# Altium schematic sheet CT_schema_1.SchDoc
size 715 x 456 mm
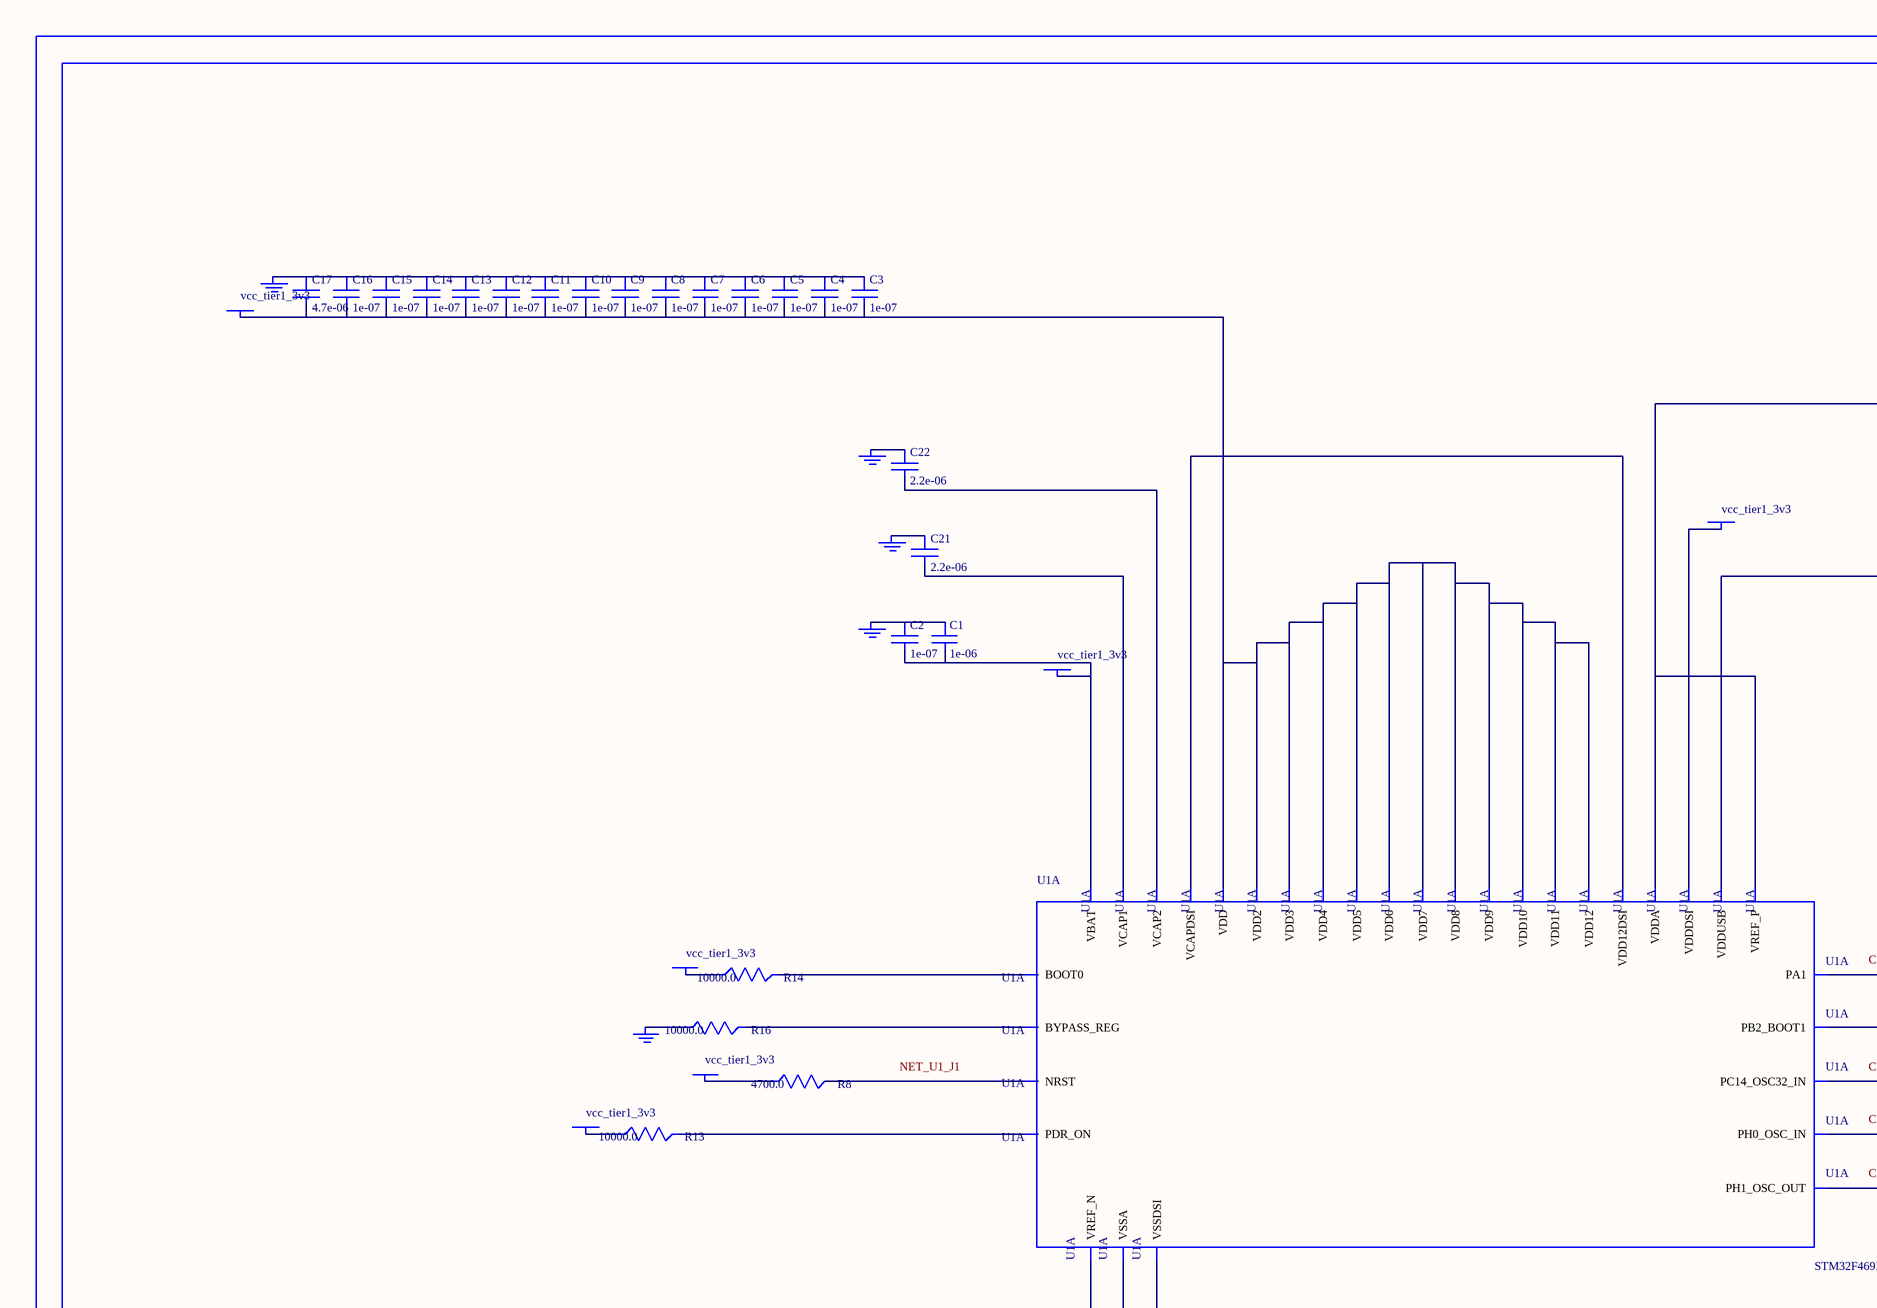
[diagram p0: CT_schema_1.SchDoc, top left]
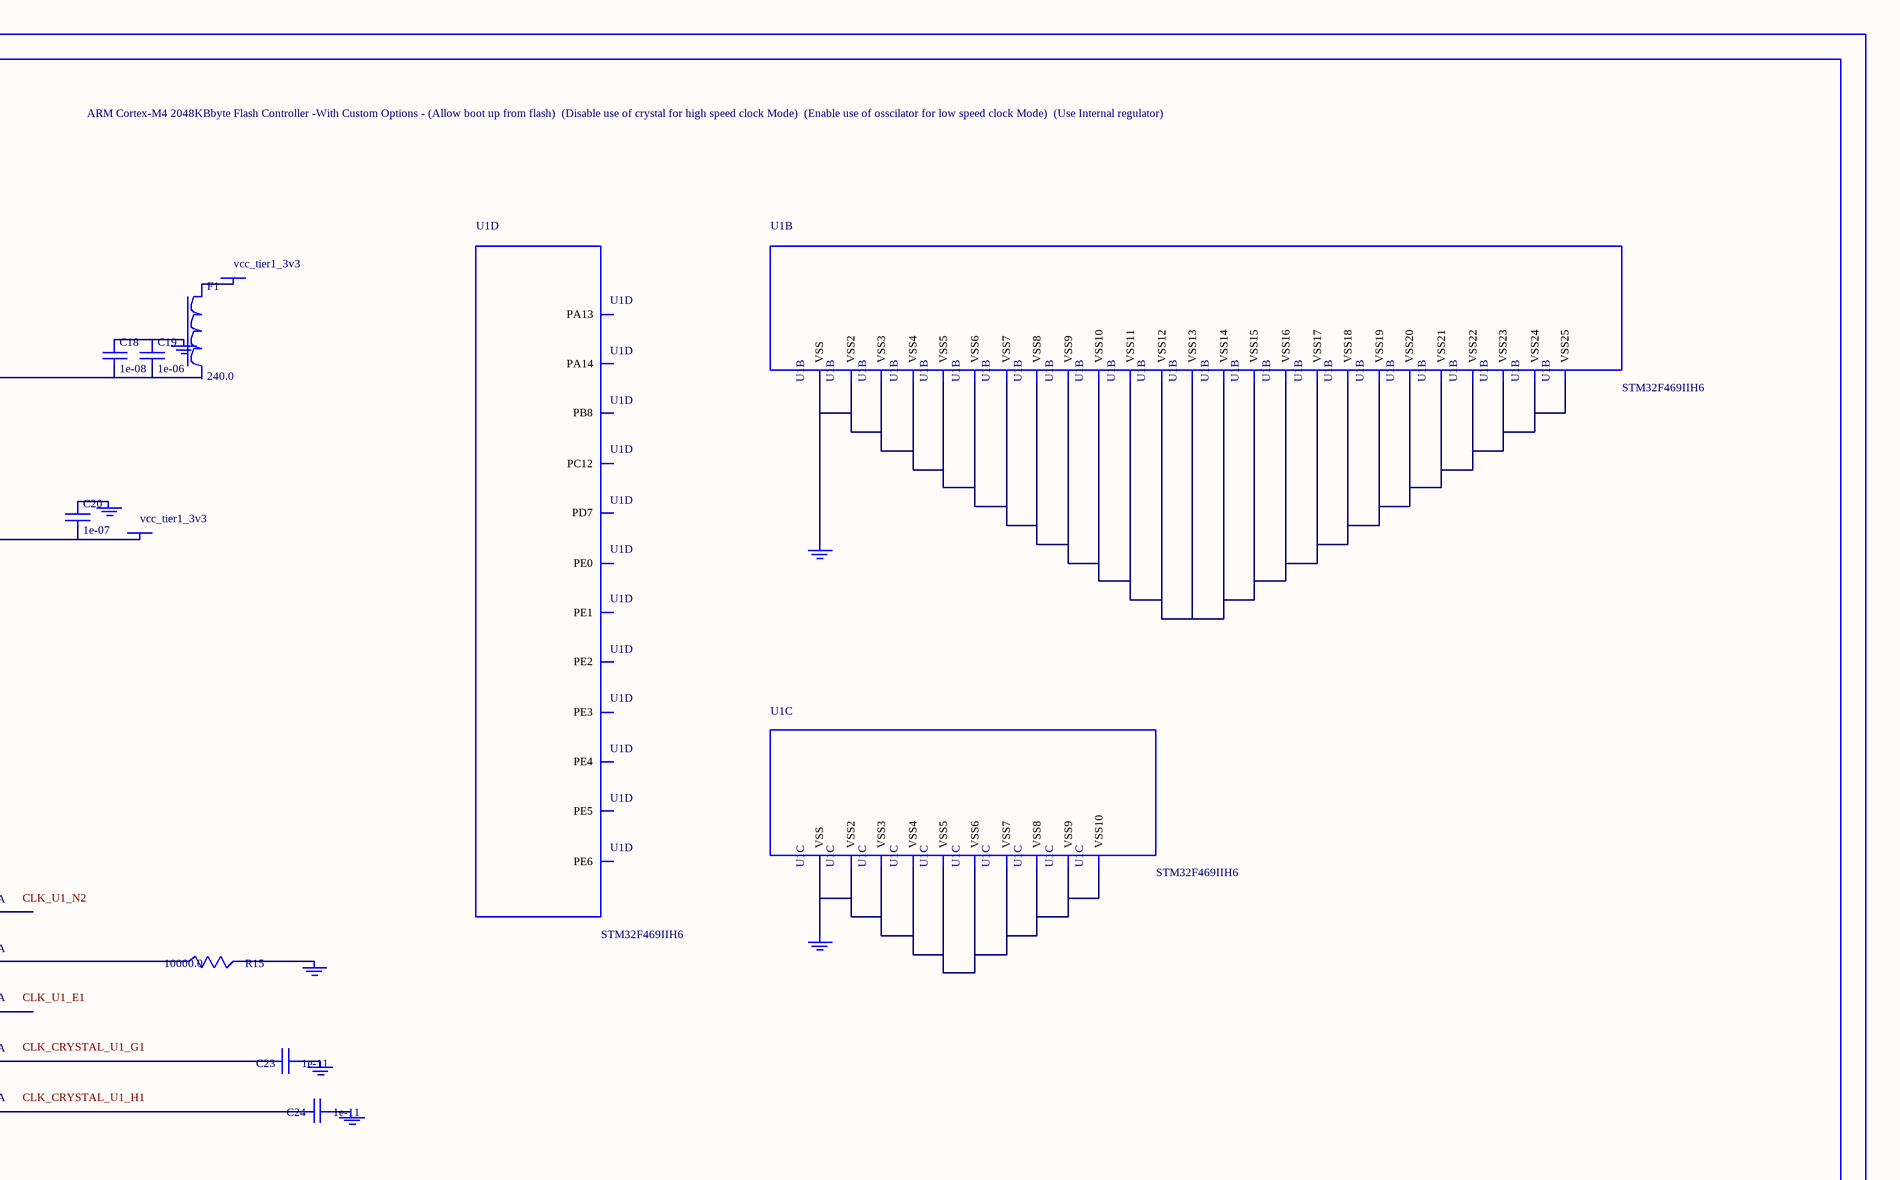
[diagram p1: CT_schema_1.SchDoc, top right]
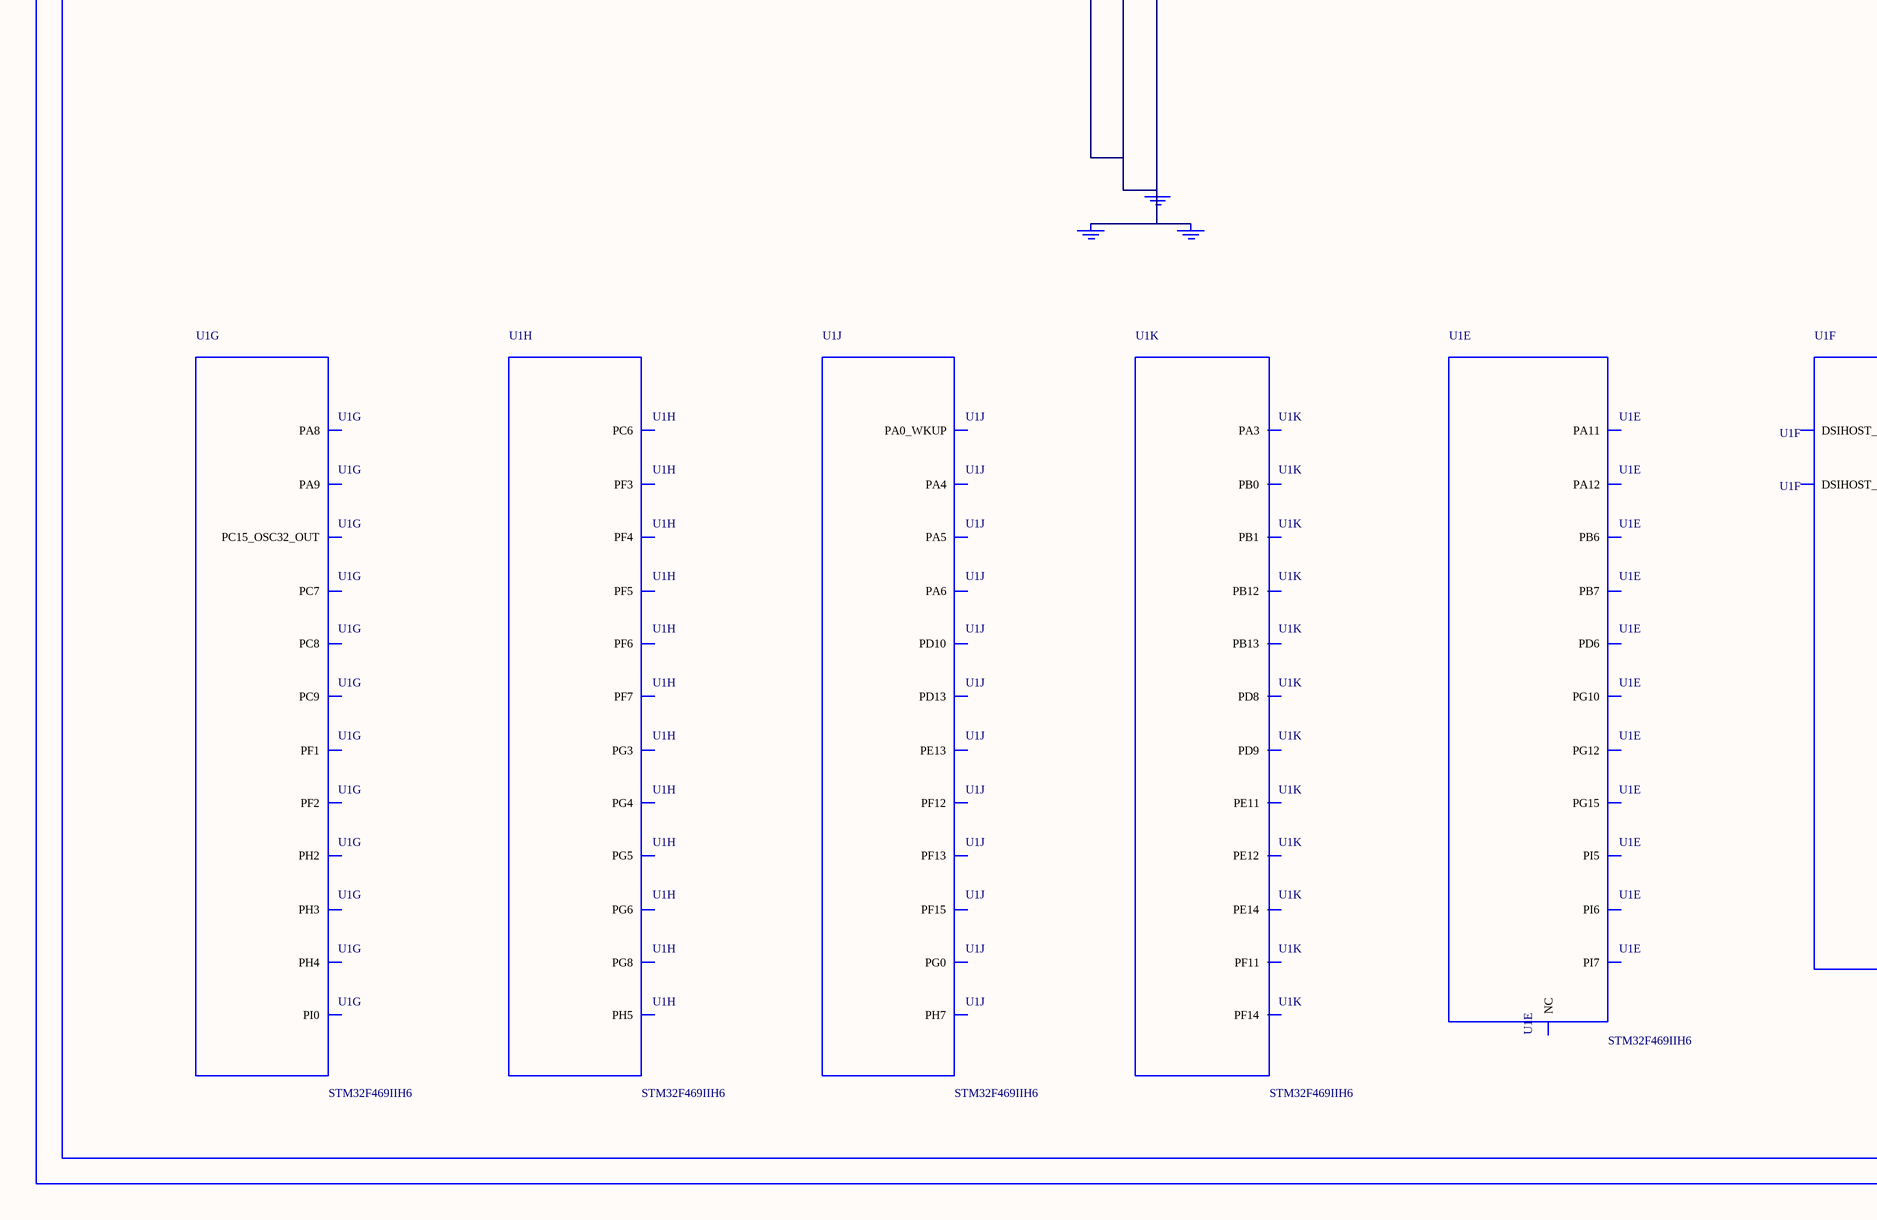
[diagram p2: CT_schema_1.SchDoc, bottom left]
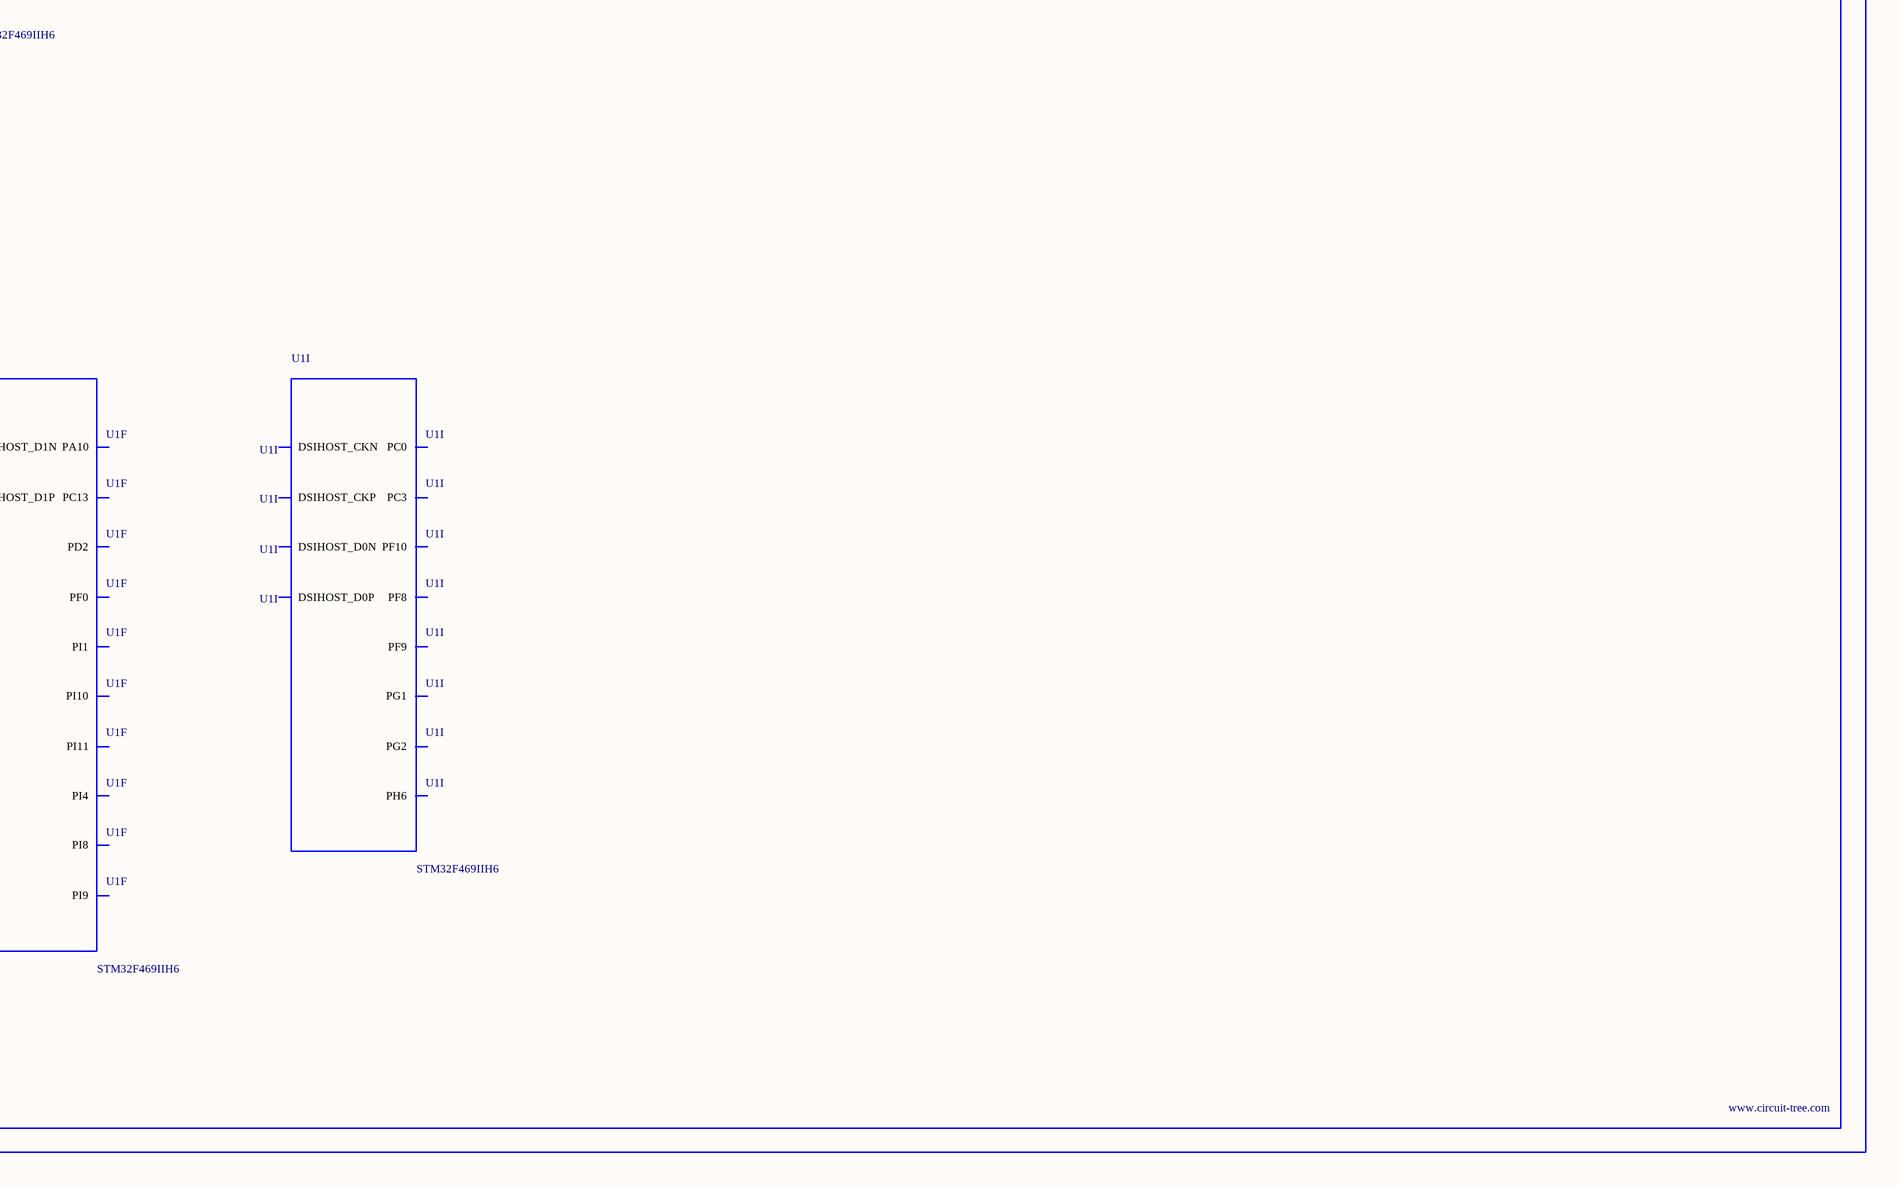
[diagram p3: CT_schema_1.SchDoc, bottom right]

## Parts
BORDER0  (no value)
C1  1e-06  [C0603]
C2  1e-07  [C0603]
C3  1e-07  [C0603]
C4  1e-07  [C0603]
C5  1e-07  [C0603]
C6  1e-07  [C0603]
C7  1e-07  [C0603]
C8  1e-07  [C0603]
C9  1e-07  [C0603]
C10  1e-07  [C0603]
C11  1e-07  [C0603]
C12  1e-07  [C0603]
C13  1e-07  [C0603]
C14  1e-07  [C0603]
C15  1e-07  [C0603]
C16  1e-07  [C0603]
C17  4.7e-06  [C0603]
C18  1e-08  [C0603]
C19  1e-06  [C0603]
C20  1e-07  [C0603]
C21  2.2e-06  [C0603]
C22  2.2e-06  [C0603]
C23  1e-11  [C0402]
C24  1e-11  [C0402]
F1  240.0  [L0603]
GND_INSTANCE_0_0  (no value)
GND_INSTANCE_0_1  (no value)
GND_INSTANCE_0_2  (no value)
GND_INSTANCE_0_3  (no value)
GND_INSTANCE_0_4  (no value)
GND_INSTANCE_0_5  (no value)
GND_INSTANCE_0_6  (no value)
GND_INSTANCE_0_7  (no value)
GND_INSTANCE_0_8  (no value)
GND_INSTANCE_0_9  (no value)
GND_INSTANCE_0_10  (no value)
GND_INSTANCE_0_11  (no value)
GND_INSTANCE_0_12  (no value)
GND_INSTANCE_0_13  (no value)
GND_INSTANCE_0_14  (no value)
POWER_INSTANCE_0_0  vcc_tier1_3v3
POWER_INSTANCE_0_1  vcc_tier1_3v3
POWER_INSTANCE_0_2  vcc_tier1_3v3
POWER_INSTANCE_0_3  vcc_tier1_3v3
POWER_INSTANCE_0_4  vcc_tier1_3v3
POWER_INSTANCE_0_5  vcc_tier1_3v3
POWER_INSTANCE_0_6  vcc_tier1_3v3
POWER_INSTANCE_0_7  vcc_tier1_3v3
R8  4700.0  [R0603]
R13  10000.0  [R0603]
R14  10000.0  [R0603]
R15  10000.0  [R0603]
R16  10000.0  [R0603]
U1  STM32F469IIH6  [UFBGA176]  (parts A,B,C,D,E,F,G,H,I,J,K of 17)

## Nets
NetC1_1: C1.1 C2.1 GND_INSTANCE_0_0.0(GND)
NetC1_2: C1.2 C2.2 POWER_INSTANCE_0_0.0(PWR) U1.C1(VBAT)
NetC3_1: C3.1 C4.1 C5.1 C6.1 C7.1 C8.1 C9.1 C10.1 C11.1 C12.1 C13.1 C14.1 C15.1 C16.1 C17.1 GND_INSTANCE_0_2.0(GND)
NetC3_2: C3.2 C4.2 C5.2 C6.2 C7.2 C8.2 C9.2 C10.2 C11.2 C12.2 C13.2 C14.2 C15.2 C16.2 C17.2 POWER_INSTANCE_0_2.0(PWR) U1.C5(VDD) U1.C7(VDD2) U1.C8(VDD3) U1.C9(VDD4) U1.F3(VDD5) U1.G3(VDD7) U1.G13(VDD6) U1.J13(VDD8) U1.K4(VDD9) U1.N8(VDD11) U1.N9(VDD12) U1.N10(VDD10)
NetC18_1: C18.1 C19.1 GND_INSTANCE_0_1.0(GND)
NetC18_2: C18.2 C19.2 U1.P1(VREF_P) U1.R1(VDDA)
NetC20_1: C20.1 GND_INSTANCE_0_3.0(GND)
NetC20_2: C20.2 POWER_INSTANCE_0_4.0(PWR) U1.H13(VDDUSB)
NetC21_1: C21.1 GND_INSTANCE_0_6.0(GND)
NetC21_2: C21.2 U1.M10(VCAP1)
NetC22_1: C22.1 GND_INSTANCE_0_7.0(GND)
NetC22_2: C22.2 U1.F13(VCAP2)
NetC23_1: C23.1 GND_INSTANCE_0_8.0(GND)
NetC23_2: C23.2 U1.G1(PH0_OSC_IN)
NetC24_1: C24.1 GND_INSTANCE_0_9.0(GND)
NetC24_2: C24.2 U1.H1(PH1_OSC_OUT)
NetF1_1: F1.1 POWER_INSTANCE_0_1.0(PWR)
NetGND_INSTANCE_0_4_0: GND_INSTANCE_0_4.0(GND) R15.2
NetGND_INSTANCE_0_5_0: GND_INSTANCE_0_5.0(GND) R16.1
NetGND_INSTANCE_0_10_0: GND_INSTANCE_0_10.0(GND) GND_INSTANCE_0_11.0(GND) GND_INSTANCE_0_12.0(GND) U1.H12(VSSDSI) U1.M1(VSSA) U1.N1(VREF_N)
NetGND_INSTANCE_0_13_0: GND_INSTANCE_0_13.0(GND) U1.D5(VSS) U1.D7(VSS2) U1.D8(VSS3) U1.D9(VSS4) U1.F2(VSS7) U1.F6(VSS8) U1.F7(VSS9) U1.F8(VSS10) U1.F9(VSS11) U1.F10(VSS5) U1.F12(VSS6) U1.G2(VSS14) U1.G6(VSS15) U1.G7(VSS16) U1.G8(VSS17) U1.G9(VSS18) U1.G10(VSS12) U1.G12(VSS13) U1.H6(VSS20) U1.H7(VSS21) U1.H8(VSS22) U1.H9(VSS23) U1.H10(VSS19) U1.J6(VSS25) U1.J10(VSS24)
NetGND_INSTANCE_0_14_0: GND_INSTANCE_0_14.0(GND) U1.J7(VSS) U1.J8(VSS2) U1.J9(VSS3) U1.K6(VSS5) U1.K7(VSS6) U1.K8(VSS7) U1.K9(VSS8) U1.K10(VSS4) U1.M8(VSS9) U1.M9(VSS10)
NetPOWER_INSTANCE_0_3_0: POWER_INSTANCE_0_3.0(PWR) R13.1
NetPOWER_INSTANCE_0_5_0: POWER_INSTANCE_0_5.0(PWR) R14.1
NetPOWER_INSTANCE_0_6_0: POWER_INSTANCE_0_6.0(PWR) U1.J12(VDDDSI)
NetPOWER_INSTANCE_0_7_0: POWER_INSTANCE_0_7.0(PWR) R8.1
NetR8_2: R8.2 U1.J1(NRST)
NetR13_2: R13.2 U1.C6(PDR_ON)
NetR14_2: R14.2 U1.D6(BOOT0)
NetR15_1: R15.1 U1.M6(PB2_BOOT1)
NetR16_2: R16.2 U1.L4(BYPASS_REG)
NetU1_D13: U1.D13(VDD12DSI) U1.K12(VCAPDSI)

Not connected (* = marked no-connect by the designer): F1 2; U1 A1(PE3) A2(PE2) A3(PE1) A4(PE0) A5(PB8) A11(PD7) A12(PC12) A14(PA14) A15(PA13) B1(PE4) B2(PE5) B3(PE6) B5(PB7) B6(PB6) B7(PG15) B8(PG12) B10(PG10) B11(PD6) B15(PA12) C2(PI7) C3(PI6) C4(PI5) C14(NC) C15(PA11) D1(PC13) D2(PI8) D3(PI9) D4(PI4) D12(PD2) D14(PI1) D15(PA10) E1(PC14_OSC32_IN) E2(PF0) E3(PI10) E4(PI11) E12(DSIHOST_D1P) E13(DSIHOST_D1N) E14(PI0) E15(PA9) F1(PC15_OSC32_OUT) F4(PH2) F14(PC9) F15(PA8) G4(PH3) G14(PC8) G15(PC7) H2(PF2) H3(PF1) H4(PH4) H14(PG8) H15(PC6) J2(PF3) J3(PF4) J4(PH5) J15(PG6) K1(PF7) K2(PF6) K3(PF5) K13(PG5) K14(PG4) K15(PG3) L1(PF10) L2(PF9) L3(PF8) L12(DSIHOST_CKP) L13(DSIHOST_CKN) L15(PG2) M2(PC0) M5(PC3) M7(PG1) M11(PH6) M12(DSIHOST_D0P) M13(DSIHOST_D0N) M15(PD13) N2(PA1) N3(PA0_WKUP) N4(PA4) N6(PF13) N7(PG0) N11(PE13) N12(PH7) N15(PD10) P3(PA6) P4(PA5) P6(PF12) P7(PF15) P10(PE11) P11(PE14) P12(PB12) P13(PB13) P14(PD9) P15(PD8) R2(PA3) R4(PB1) R5(PB0) R6(PF11) R7(PF14) R10(PE12)

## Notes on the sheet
- Labels drawn without touching a wire or pin: CLK_CRYSTAL_U1_G1, CLK_CRYSTAL_U1_H1, CLK_U1_E1, CLK_U1_N2, NET_U1_J1

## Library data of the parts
BORDER0 = BORDER_PAGE0
C1 C19 = C0603C105K3RACTU
C2-C16 C20 = 06035C104K4Z2A
C17 = GRM188R6YA475KE15D
C18 = 06035C103K4Z2A
C21 C22 = C0603C225K8RACTU
C23 C24 = C0402C100K3GACTU
F1 = Z0603C241ASMST
GND_INSTANCE_0_0-GND_INSTANCE_0_14 = GND
POWER_INSTANCE_0_0-POWER_INSTANCE_0_7 = PWR
R8 = RC0603JR-074K7L
R13-R16 = RC0603JR-0710KL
